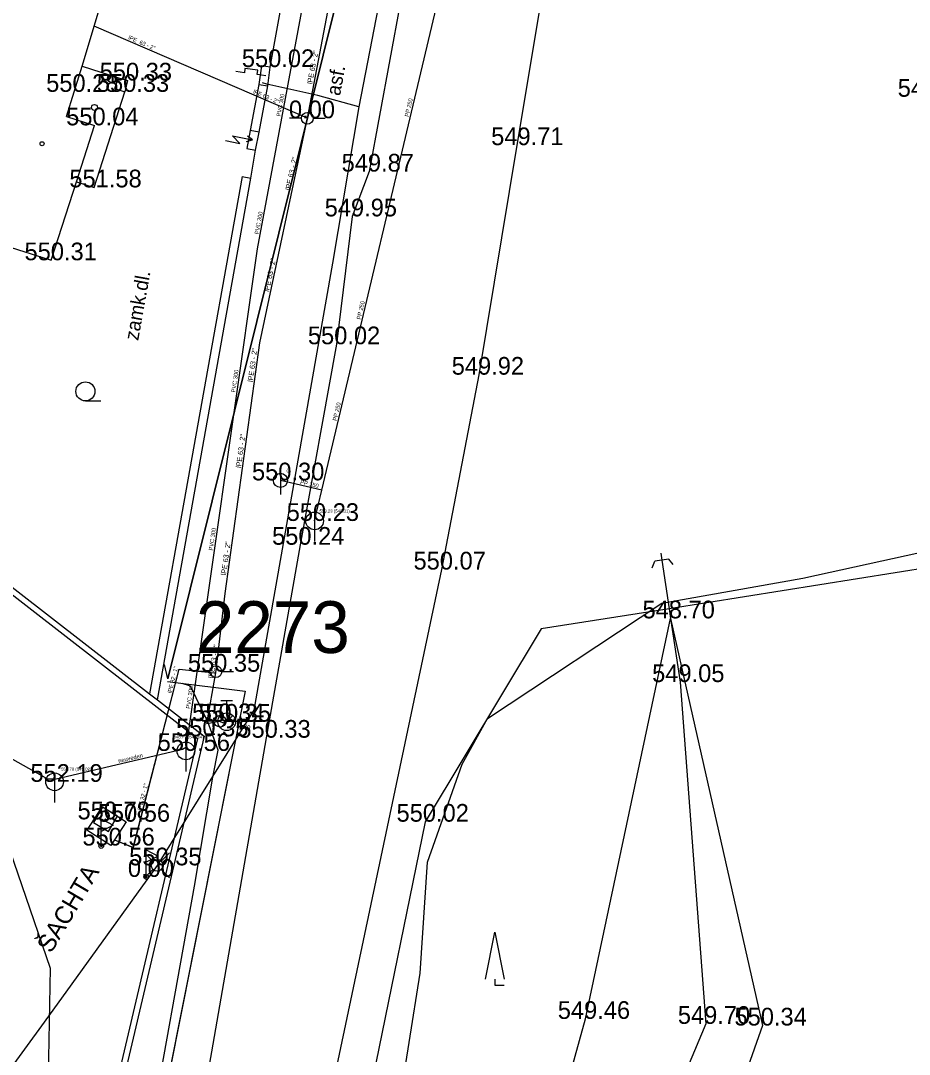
# Model space of a CAD drawing. Extents: x -669995 to -669686, y -1125551 to -1125263.
# Drawn here: x -669866.53 to -669828.84, y -1125464.59 to -1125420.77 of the extents above; entities that cross this region are included whole.
import ezdxf

# ---------------------------------------------------------------- set-up
doc = ezdxf.new("R2010")
doc.units = 0
for name, color, linetype in [('G_Bod_tecka', 7, 'Continuous'), ('G_Bod_vyska', 7, 'Continuous'), ('G_Breh_Teren', 7, 'Continuous'), ('G_Budovy-znacky', 7, 'Continuous'), ('G_Budovy_Objekty', 7, 'Continuous'), ('G_Budovy_vstupy', 7, 'Continuous'), ('G_Cesty_Schody', 7, 'Continuous'), ('G_Plochy_zpevnene', 7, 'Continuous'), ('G_Ploty', 7, 'Continuous'), ('G_Ploty_vstupy', 7, 'Continuous'), ('G_Popisy_povrchu', 7, 'Continuous'), ('G_Poznamky_odkaz', 7, 'Continuous'), ('G_Site-kanalizace', 7, 'Continuous'), ('G_Site-plynovod', 7, 'Continuous'), ('G_Site-Rozvadece', 7, 'Continuous'), ('G_Site-Sachty_N', 7, 'Continuous'), ('G_Site-vodovod', 7, 'Continuous'), ('G_Z_ELsilove_nadz_kotovane', 7, 'Continuous'), ('G_Z_ELsilove_podz_kotovane', 7, 'Continuous'), ('G_Z_KANAL_podz_kotovane', 7, 'Continuous'), ('G_Z_KANAL_podz_priblizne', 7, 'Continuous'), ('G_Z_PLYNY_podz_geodeticky', 7, 'Continuous'), ('G_Z_SPOJE_podz_geodeticky', 7, 'Continuous'), ('G_Z_VODA_podz_kotovane', 7, 'Continuous'), ('G_Zelen-okraj', 7, 'Continuous'), ('G_Zelen-Znacky', 7, 'Continuous'), ('Vrstva 1', 7, 'Continuous'), ('Vrstva 11', 7, 'Continuous'), ('Vrstva 13', 7, 'Continuous'), ('Vrstva 17', 7, 'Continuous'), ('Vrstva 2', 7, 'Continuous'), ('Vrstva 26', 7, 'Continuous'), ('Vrstva 3', 7, 'Continuous'), ('Vrstva 4', 7, 'Continuous'), ('Vrstva 5', 7, 'Continuous'), ('Vrstva 6', 7, 'Continuous'), ('Vrstva 7', 7, 'Continuous'), ('Vrstva 8', 7, 'Continuous')]:
    doc.layers.add(name, color=color, linetype=linetype)

msp = doc.modelspace()

# ---------------------------------------------------------------- linework, layer by layer
at = {"layer": 'G_Bod_tecka'}
for p, q in [((-669855.94, -1125422.74), (-669855.94, -1125422.74)), ((-669861.99, -1125423.31), (-669861.99, -1125423.31)), ((-669864.26, -1125423.79), (-669864.26, -1125423.79)), ((-669862.11, -1125423.79), (-669862.11, -1125423.79)), ((-669854.37, -1125424.91), (-669854.37, -1125424.91)), ((-669863.39, -1125425.21), (-669863.39, -1125425.21)), ((-669845.47, -1125426.05), (-669845.47, -1125426.05)), ((-669851.75, -1125427.17), (-669851.75, -1125427.17)), ((-669863.44, -1125427.84), (-669863.44, -1125427.84)), ((-669852.47, -1125429.07), (-669852.47, -1125429.07)), ((-669865.24, -1125430.93), (-669865.24, -1125430.93)), ((-669853.14, -1125434.49), (-669853.14, -1125434.49)), ((-669847.08, -1125435.78), (-669847.08, -1125435.78)), ((-669855.51, -1125440.26), (-669855.51, -1125440.26)), ((-669854.06, -1125441.98), (-669854.06, -1125441.98)), ((-669854.68, -1125442.99), (-669854.68, -1125442.99)), ((-669848.66, -1125444.04), (-669848.66, -1125444.04)), ((-669838.97, -1125446.11), (-669838.97, -1125446.11)), ((-669858.25, -1125448.37), (-669858.25, -1125448.37)), ((-669838.56, -1125448.81), (-669838.56, -1125448.81)), ((-669858.07, -1125450.47), (-669858.07, -1125450.47)), ((-669857.79, -1125450.49), (-669857.79, -1125450.49)), ((-669858.75, -1125451.11), (-669858.75, -1125451.11)), ((-669856.11, -1125451.17), (-669856.11, -1125451.17)), ((-669859.52, -1125451.73), (-669859.52, -1125451.73)), ((-669865.09, -1125453.04), (-669865.09, -1125453.04)), ((-669862.93, -1125454.63), (-669862.93, -1125454.63)), ((-669862.06, -1125454.73), (-669862.06, -1125454.73)), ((-669849.38, -1125454.73), (-669849.38, -1125454.73)), ((-669862.71, -1125455.74), (-669862.71, -1125455.74)), ((-669860.74, -1125456.58), (-669860.74, -1125456.58)), ((-669861.2, -1125457.07), (-669861.2, -1125457.07)), ((-669842.57, -1125463.09), (-669842.57, -1125463.09)), ((-669837.47, -1125463.3), (-669837.47, -1125463.3)), ((-669835.07, -1125463.37), (-669835.07, -1125463.37))]:
    msp.add_line(p, q, dxfattribs=at)
at = {"layer": 'G_Breh_Teren'}
for p, q in [((-669839.34, -1125443.64), (-669839.03, -1125445.7)), ((-669839.03, -1125445.7), (-669838.97, -1125446.11)), ((-669842.57, -1125463.09), (-669838.97, -1125446.11)), ((-669838.97, -1125446.11), (-669835.07, -1125463.37)), ((-669838.97, -1125446.11), (-669838.56, -1125448.81)), ((-669838.56, -1125448.81), (-669837.47, -1125463.3)), ((-669845.79, -1125474.65), (-669842.57, -1125463.09))]:
    msp.add_line(p, q, dxfattribs=at)
for points in [[(-669837.47, -1125463.3), (-669842.14, -1125474.41)], [(-669835.07, -1125463.37), (-669838.97, -1125474.44)]]:
    msp.add_lwpolyline(points, dxfattribs=at)
at = {"layer": 'G_Budovy-znacky'}
for centre, radius in [((-669863.4, -1125424.45), 0.125), ((-669865.619, -1125425.99), 0.0875)]:
    msp.add_circle(centre, radius, dxfattribs=at)
at = {"layer": 'G_Budovy_Objekty'}
for p, q in [((-669863.92, -1125422.7), (-669863.19, -1125420.26)), ((-669864.26, -1125423.79), (-669863.92, -1125422.7)), ((-669863.92, -1125422.7), (-669862.38, -1125423.19)), ((-669862.53, -1125423.65), (-669862.38, -1125423.19)), ((-669862.38, -1125423.19), (-669861.99, -1125423.31)), ((-669861.99, -1125423.31), (-669862.11, -1125423.79)), ((-669863.41, -1125427.84), (-669862.11, -1125423.79)), ((-669862.53, -1125423.65), (-669862.11, -1125423.79)), ((-669864.58, -1125424.83), (-669863.39, -1125425.21)), ((-669864.16, -1125427.6), (-669863.39, -1125425.21)), ((-669877.15, -1125427.12), (-669865.24, -1125430.93)), ((-669865.24, -1125430.93), (-669864.16, -1125427.6)), ((-669864.16, -1125427.6), (-669863.41, -1125427.84))]:
    msp.add_line(p, q, dxfattribs=at)
at = {"layer": 'G_Budovy_vstupy'}
msp.add_line((-669864.58, -1125424.83), (-669864.26, -1125423.79), dxfattribs=at)
at = {"layer": 'G_Cesty_Schody'}
for p, q in [((-669863.07, -1125454.08), (-669863.72, -1125455.09)), ((-669863.07, -1125454.08), (-669862.06, -1125454.73)), ((-669862.06, -1125454.73), (-669862.71, -1125455.74)), ((-669862.71, -1125455.74), (-669863.72, -1125455.09))]:
    msp.add_line(p, q, dxfattribs=at)
at = {"layer": 'G_Plochy_zpevnene'}
for p, q in [((-669845.47, -1125426.05), (-669843.77, -1125415.85)), ((-669850.43, -1125420.04), (-669851.75, -1125427.17)), ((-669847.08, -1125435.78), (-669845.47, -1125426.05)), ((-669851.75, -1125427.17), (-669852.47, -1125429.07)), ((-669852.47, -1125429.07), (-669853.14, -1125434.49)), ((-669853.14, -1125434.49), (-669854.68, -1125442.99)), ((-669848.66, -1125444.04), (-669847.08, -1125435.78)), ((-669857.76, -1125487.1), (-669848.66, -1125444.04))]:
    msp.add_line(p, q, dxfattribs=at)
msp.add_lwpolyline([(-669854.68, -1125442.99), (-669856.11, -1125451.17), (-669858.7, -1125466.02)], dxfattribs=at)
at = {"layer": 'G_Ploty'}
for p, q in [((-669856.43, -1125423.48), (-669856.79, -1125425.43)), ((-669856.42, -1125425.5), (-669856.05, -1125423.53)), ((-669857.14, -1125427.38), (-669861.07, -1125449.31)), ((-669860.73, -1125449.57), (-669856.77, -1125427.45)), ((-669857.14, -1125427.38), (-669856.77, -1125427.45)), ((-669878.91, -1125435.78), (-669859.03, -1125451.21)), ((-669859.03, -1125451.21), (-669864.64, -1125475.11)), ((-669858.75, -1125451.11), (-669864.36, -1125475.01))]:
    msp.add_line(p, q, dxfattribs=at)
msp.add_lwpolyline([(-669879.12, -1125435.3), (-669861.07, -1125449.31), (-669860.73, -1125449.57), (-669858.75, -1125451.11)], dxfattribs=at)
at = {"layer": 'G_Ploty_vstupy'}
for p, q in [((-669855.94, -1125422.74), (-669855.39, -1125419.71)), ((-669856.77, -1125427.45), (-669856.57, -1125426.26))]:
    msp.add_line(p, q, dxfattribs=at)
at = {"layer": 'G_Site-kanalizace'}
for p, q in [((-669855.51, -1125439.96), (-669855.51, -1125440.86)), ((-669854.06, -1125441.605), (-669854.06, -1125442.855)), ((-669839.385, -1125443.343), (-669839.34, -1125443.64)), ((-669839.746, -1125443.965), (-669839.637, -1125443.685)), ((-669839.34, -1125443.64), (-669839.637, -1125443.685)), ((-669839.043, -1125443.595), (-669839.34, -1125443.64)), ((-669838.856, -1125443.83), (-669839.043, -1125443.595)), ((-669859.52, -1125451.355), (-669859.52, -1125452.605)), ((-669865.09, -1125452.665), (-669865.09, -1125453.915))]:
    msp.add_line(p, q, dxfattribs=at)
for centre, radius in [((-669855.51, -1125440.26), 0.3), ((-669854.06, -1125441.98), 0.375), ((-669859.52, -1125451.73), 0.375), ((-669865.09, -1125453.04), 0.375)]:
    msp.add_circle(centre, radius, dxfattribs=at)
at = {"layer": 'G_Site-plynovod'}
for p, q in [((-669863.11, -1125455.76), (-669863.11, -1125454.61)), ((-669863.11, -1125454.61), (-669862.61, -1125454.875)), ((-669862.61, -1125454.875), (-669863.11, -1125455.14)), ((-669861.272, -1125456.048), (-669860.917, -1125456.403)), ((-669861.2, -1125457.07), (-669861.2, -1125455.92)), ((-669861.2, -1125455.92), (-669860.7, -1125456.185)), ((-669860.7, -1125456.185), (-669861.2, -1125456.45)), ((-669860.563, -1125456.402), (-669860.209, -1125456.049)), ((-669860.917, -1125456.756), (-669861.27, -1125457.11)), ((-669860.564, -1125456.755), (-669860.209, -1125457.11))]:
    msp.add_line(p, q, dxfattribs=at)
for centre, radius in [((-669863.11, -1125455.76), 0.1), ((-669863.11, -1125455.76), 0.0348), ((-669860.74, -1125456.58), 0.25), ((-669861.2, -1125457.07), 0.1), ((-669861.2, -1125457.07), 0.0348)]:
    msp.add_circle(centre, radius, dxfattribs=at)
at = {"layer": 'G_Site-Rozvadece'}
for p, q in [((-669857.843, -1125425.858), (-669857.228, -1125425.979)), ((-669857.228, -1125425.979), (-669857.548, -1125425.661)), ((-669857.548, -1125425.661), (-669856.69, -1125425.83)), ((-669856.951, -1125425.891), (-669856.69, -1125425.83)), ((-669856.69, -1125425.83), (-669856.909, -1125425.675))]:
    msp.add_line(p, q, dxfattribs=at)
msp.add_lwpolyline([(-669856.13, -1125423.11), (-669856.494, -1125423.059), (-669856.469, -1125422.877), (-669857.015, -1125422.801), (-669857.042, -1125422.982), (-669857.406, -1125422.933)], dxfattribs=at)
for points in [[(-669855.94, -1125422.74), (-669856.32, -1125422.69), (-669856.43, -1125423.48), (-669856.05, -1125423.53)], [(-669856.42, -1125425.5), (-669856.79, -1125425.43), (-669856.94, -1125426.19), (-669856.57, -1125426.26)]]:
    msp.add_lwpolyline(points, close=True, dxfattribs=at)
at = {"layer": 'G_Site-Sachty_N'}
msp.add_lwpolyline([(-669863.444, -1125454.762), (-669862.798, -1125455.144), (-669862.416, -1125454.498), (-669863.062, -1125454.116)], close=True, dxfattribs=at)
msp.add_circle((-669862.93, -1125454.63), 0.02, dxfattribs=at)
at = {"layer": 'G_Site-vodovod'}
for p, q in [((-669854.62, -1125424.91), (-669855.12, -1125424.91)), ((-669854.12, -1125424.91), (-669853.62, -1125424.91)), ((-669858.5, -1125448.37), (-669859, -1125448.37)), ((-669858, -1125448.37), (-669857.5, -1125448.37)), ((-669858.04, -1125449.59), (-669857.54, -1125449.59)), ((-669857.79, -1125450.115), (-669857.79, -1125449.59)), ((-669858.32, -1125450.47), (-669858.82, -1125450.47)), ((-669858.055, -1125450.755), (-669857.525, -1125450.225)), ((-669857.82, -1125450.47), (-669857.32, -1125450.47))]:
    msp.add_line(p, q, dxfattribs=at)
for centre, radius in [((-669854.37, -1125424.91), 0.25), ((-669858.25, -1125448.37), 0.25), ((-669857.79, -1125450.49), 0.375), ((-669858.07, -1125450.47), 0.25)]:
    msp.add_circle(centre, radius, dxfattribs=at)
at = {"layer": 'G_Z_ELsilove_nadz_kotovane'}
for points in [[(-669860.28, -1125448.68), (-669849.93, -1125407.07)], [(-669860.28, -1125448.68), (-669860.43, -1125448.062)]]:
    msp.add_lwpolyline(points, dxfattribs=at)
at = {"layer": 'G_Z_ELsilove_podz_kotovane'}
for points in [[(-669793.678, -1125277.309), (-669806.73, -1125294.49), (-669822.69, -1125326.67), (-669837.43, -1125364.93), (-669849.93, -1125407.07), (-669860.28, -1125448.68)], [(-669863.576, -1125550.524), (-669862.33, -1125537.01), (-669860.37, -1125518.38), (-669858.01, -1125505.29), (-669856.03, -1125494.7), (-669852.89, -1125480.26), (-669850.98, -1125469.97), (-669849.59, -1125461.15), (-669849.27, -1125456.45), (-669847.81, -1125452.29), (-669846.73, -1125450.36), (-669839.33, -1125445.47), (-669833.36, -1125444.41), (-669826.21, -1125442.84), (-669824.2, -1125441.7), (-669823.97, -1125438.88), (-669824.78, -1125429.63), (-669825.67, -1125424.25), (-669825.82, -1125421.69), (-669825.4, -1125420.37)], [(-669860.3, -1125448.78), (-669857.01, -1125449.2), (-669865.7, -1125492.91), (-669865.7, -1125492.92), (-669866.34, -1125496.64), (-669873.15, -1125519.21), (-669881.89, -1125548.16)], [(-669883.381, -1125547.971), (-669882.5, -1125544.29), (-669880.2, -1125536.8), (-669877.05, -1125527.79), (-669873.99, -1125518.65), (-669873.17, -1125517.76), (-669871.78, -1125517.42), (-669870.84, -1125517.03), (-669870.63, -1125516.39), (-669866.12, -1125495.04), (-669865.96, -1125494.25), (-669863.58, -1125480.59), (-669861.15, -1125468.54), (-669859.15, -1125457.46), (-669858.38, -1125452.84), (-669858.15, -1125451.7), (-669858.59, -1125450.49), (-669859.33, -1125448.99), (-669859.674, -1125448.873)]]:
    msp.add_lwpolyline(points, dxfattribs=at)
at = {"layer": 'G_Z_KANAL_podz_kotovane'}
msp.add_line((-669853.75, -1125440.68), (-669855.51, -1125440.26), dxfattribs=at)
for points in [[(-669854.06, -1125441.98), (-669853.75, -1125440.68), (-669848.77, -1125419.63), (-669845.09, -1125404.08), (-669844.67, -1125402.32)], [(-669884.87, -1125442.37), (-669884.3, -1125442.3), (-669865.39, -1125452.91), (-669865.02, -1125452.92), (-669859.66, -1125451.66), (-669859.5, -1125451.55)]]:
    msp.add_lwpolyline(points, dxfattribs=at)
at = {"layer": 'G_Z_KANAL_podz_priblizne'}
msp.add_lwpolyline([(-669859.5, -1125451.55), (-669856.48, -1125430.45), (-669853.73, -1125415.63), (-669852.14, -1125407.38), (-669851.85, -1125406.81), (-669846.78, -1125392.66), (-669840.64, -1125375.45), (-669843.45, -1125370.23)], dxfattribs=at)
at = {"layer": 'G_Z_PLYNY_podz_geodeticky'}
for points in [[(-669839.68, -1125381.34), (-669843.56, -1125391.5), (-669845.77, -1125398.22), (-669846.85, -1125401.64), (-669847.2, -1125402.75), (-669848.28, -1125405.76), (-669848.45, -1125406.31), (-669848.51, -1125406.54), (-669849.81, -1125412.17), (-669852.19, -1125424.43), (-669853.31, -1125431.05), (-669856.64, -1125450), (-669860.14, -1125455.63), (-669860.74, -1125456.58)], [(-669852.19, -1125424.43), (-669853.93, -1125423.95), (-669856.09, -1125423.46), (-669856.27, -1125423.41)], [(-669860.74, -1125456.58), (-669864.36, -1125461.6), (-669865.53, -1125463.23), (-669867.2, -1125465.52), (-669868.44, -1125468.41), (-669874.13, -1125486.27), (-669879.55, -1125501.34), (-669881.43, -1125507.04), (-669885.9, -1125530.75), (-669889.237, -1125547.216)]]:
    msp.add_lwpolyline(points, dxfattribs=at)
at = {"layer": 'G_Z_SPOJE_podz_geodeticky'}
msp.add_lwpolyline([(-669868.9, -1125450.43), (-669865.28, -1125460.94), (-669865.56, -1125476.2), (-669868.62, -1125490.28), (-669873.32, -1125500), (-669873.84, -1125501.08), (-669875.38, -1125507.75), (-669876.44, -1125519.45), (-669880.16, -1125533.89), (-669884.345, -1125547.846)], dxfattribs=at)
at = {"layer": 'G_Z_VODA_podz_kotovane'}
msp.add_line((-669854.37, -1125424.91), (-669863.41, -1125421), dxfattribs=at)
for points in [[(-669858.63, -1125450.57), (-669858.25, -1125448.42), (-669857.85, -1125445.05), (-669856.38, -1125434.43), (-669854.37, -1125424.91), (-669851.09, -1125407.69), (-669849.25, -1125402.21), (-669840.03, -1125375.63), (-669840.08, -1125374.27), (-669839.76, -1125372.61), (-669839.5, -1125370.59), (-669837.98, -1125365.03), (-669838.35, -1125363.15), (-669838.04, -1125362.68), (-669836.94, -1125362.97)], [(-669862.55, -1125455.5), (-669861.75, -1125455.82), (-669859.81, -1125448.27), (-669858.31, -1125448.42), (-669858.25, -1125448.42)], [(-669858.63, -1125450.57), (-669858.11, -1125450.47), (-669857.85, -1125450.57)]]:
    msp.add_lwpolyline(points, dxfattribs=at)
at = {"layer": 'G_Zelen-okraj'}
for p, q in [((-669824.81, -1125443.45), (-669839.03, -1125445.7)), ((-669839.03, -1125445.7), (-669844.46, -1125446.56)), ((-669844.46, -1125446.56), (-669849.38, -1125454.73)), ((-669849.38, -1125454.73), (-669853.07, -1125472.79))]:
    msp.add_line(p, q, dxfattribs=at)
at = {"layer": 'G_Zelen-Znacky'}
for p, q in [((-669863.782, -1125436.89), (-669863.132, -1125436.887)), ((-669846.82, -1125461.41), (-669846.42, -1125459.41)), ((-669846.42, -1125459.41), (-669846.02, -1125461.41)), ((-669846.42, -1125461.41), (-669846.42, -1125461.66)), ((-669846.42, -1125461.66), (-669846.02, -1125461.66))]:
    msp.add_line(p, q, dxfattribs=at)
msp.add_circle((-669863.782, -1125436.487), 0.403, dxfattribs=at)
at = {"layer": 'Vrstva 1'}
msp.add_line((-669860.3, -1125448.78), (-669860.3, -1125448.78), dxfattribs=at)
at = {"layer": 'Vrstva 11'}
msp.add_line((-669853.75, -1125440.68), (-669855.51, -1125440.26), dxfattribs=at)
msp.add_lwpolyline([(-669854.06, -1125441.98), (-669853.75, -1125440.68), (-669848.77, -1125419.63), (-669845.09, -1125404.08), (-669844.67, -1125402.32)], dxfattribs=at)
at = {"layer": 'Vrstva 13'}
msp.add_lwpolyline([(-669885.03, -1125442.78), (-669884.87, -1125442.37), (-669884.3, -1125442.3), (-669865.39, -1125452.91), (-669865.02, -1125452.92), (-669859.66, -1125451.66), (-669859.5, -1125451.55)], dxfattribs=at)
at = {"layer": 'Vrstva 17'}
for p, q in [((-669860.3, -1125448.78), (-669857.01, -1125449.2)), ((-669857.01, -1125449.2), (-669865.7, -1125492.91))]:
    msp.add_line(p, q, dxfattribs=at)
msp.add_lwpolyline([(-669859.5, -1125451.55), (-669856.48, -1125430.45), (-669853.73, -1125415.63), (-669852.14, -1125407.38), (-669851.85, -1125406.81), (-669846.78, -1125392.66), (-669840.64, -1125375.45), (-669843.45, -1125370.23)], dxfattribs=at)
at = {"layer": 'Vrstva 26'}
msp.add_line((-669854.37, -1125424.91), (-669863.411, -1125421), dxfattribs=at)
for points in [[(-669858.63, -1125450.57), (-669858.245, -1125448.421), (-669857.85, -1125445.05), (-669856.38, -1125434.43), (-669854.37, -1125424.91), (-669851.09, -1125407.69), (-669849.25, -1125402.21), (-669840.03, -1125375.63), (-669840.08, -1125374.27), (-669839.76, -1125372.61), (-669839.5, -1125370.59), (-669837.98, -1125365.03), (-669838.35, -1125363.15), (-669838.04, -1125362.68), (-669836.94, -1125362.97)], [(-669862.551, -1125455.498), (-669861.745, -1125455.825), (-669859.807, -1125448.265), (-669858.306, -1125448.415), (-669858.245, -1125448.421)], [(-669858.63, -1125450.57), (-669858.11, -1125450.47), (-669857.85, -1125450.57)]]:
    msp.add_lwpolyline(points, dxfattribs=at)
at = {"layer": 'Vrstva 5'}
msp.add_line((-669849.93, -1125407.07), (-669860.28, -1125448.68), dxfattribs=at)
at = {"layer": 'Vrstva 6'}
for p, q in [((-669854.37, -1125424.91), (-669854.37, -1125424.91)), ((-669858.306, -1125448.415), (-669858.306, -1125448.415)), ((-669858.11, -1125450.47), (-669858.11, -1125450.47))]:
    msp.add_line(p, q, dxfattribs=at)
at = {"layer": 'Vrstva 7'}
msp.add_line((-669857.85, -1125450.57), (-669857.85, -1125450.57), dxfattribs=at)
at = {"layer": 'Vrstva 8'}
for p, q in [((-669855.51, -1125440.26), (-669855.51, -1125440.26)), ((-669854.06, -1125441.98), (-669854.06, -1125441.98)), ((-669859.5, -1125451.55), (-669859.5, -1125451.55)), ((-669865.02, -1125452.92), (-669865.02, -1125452.92))]:
    msp.add_line(p, q, dxfattribs=at)

# ---------------------------------------------------------------- texts
at = {"layer": 'G_Bod_vyska'}
for s, p in [('550.02', (-669857.147, -1125422.74)), ('550.33', (-669863.176, -1125423.31)), ('550.28', (-669865.446, -1125423.79)), ('550.33', (-669863.296, -1125423.79)), ('549.13', (-669829.334, -1125424)), ('0.00', (-669855.15, -1125424.91)), ('550.04', (-669864.597, -1125425.21)), ('549.71', (-669846.574, -1125426.05)), ('549.87', (-669852.916, -1125427.17)), ('551.58', (-669864.462, -1125427.84)), ('549.95', (-669853.635, -1125429.07)), ('550.31', (-669866.364, -1125430.93)), ('550.02', (-669854.347, -1125434.49)), ('549.92', (-669848.248, -1125435.78)), ('550.30', (-669856.717, -1125440.26)), ('550.23', (-669855.246, -1125441.98)), ('550.24', (-669855.866, -1125442.99)), ('550.07', (-669849.867, -1125444.04)), ('548.70', (-669840.156, -1125446.11)), ('550.35', (-669859.436, -1125448.37)), ('549.05', (-669839.748, -1125448.81)), ('550.34', (-669859.256, -1125450.47)), ('550.35', (-669858.976, -1125450.49)), ('550.35', (-669859.936, -1125451.11)), ('550.33', (-669857.296, -1125451.17)), ('550.56', (-669860.719, -1125451.73)), ('552.19', (-669866.114, -1125453.04)), ('550.78', (-669864.116, -1125454.63)), ('550.56', (-669863.259, -1125454.73)), ('550.02', (-669850.587, -1125454.73)), ('550.56', (-669863.909, -1125455.74)), ('550.35', (-669861.926, -1125456.58)), ('0.00', (-669861.98, -1125457.07)), ('549.46', (-669843.75, -1125463.09)), ('549.70', (-669838.658, -1125463.3)), ('550.34', (-669836.256, -1125463.37))]:
    msp.add_text(s, height=0.75, dxfattribs=at).set_placement(p)
at = {"layer": 'G_Popisy_povrchu'}
for s, rotation, p in [('asf.', 79.5114, (-669852.988, -1125423.985)), ('zamk.dl.', 79.8545, (-669861.544, -1125434.362))]:
    msp.add_text(s, height=0.6, rotation=rotation, dxfattribs=at).set_placement(p)
at = {"layer": 'G_Poznamky_odkaz'}
msp.add_text('ŠACHTA', height=0.75, rotation=59.4028, dxfattribs=at).set_placement((-669865.237, -1125460.345))
at = {"layer": 'Vrstva 2'}
for s, height, p in [('\xa0()', 0.1316, (-669855.305, -1125439.907)), ('550.23 (548.01)', 0.13163, (-669853.854, -1125441.627)), ('548.77 (548.64)', 0.13163, (-669860.046, -1125451.197)), ('550.78 (549.02)', 0.13163, (-669864.814, -1125452.567))]:
    msp.add_text(s, height=height, dxfattribs=at).set_placement(p)
at = {"layer": 'Vrstva 3'}
for s, rotation, p in [('PVC 300', 79.537, (-669855.511, -1125424.843)), ('PP 250', 76.7029, (-669850.078, -1125424.862)), ('PVC 300', 79.537, (-669856.437, -1125429.838)), ('PP 250', 76.6934, (-669852.115, -1125433.455)), ('PVC 300', 81.8747, (-669857.423, -1125436.54)), ('PP 250', 76.7029, (-669853.132, -1125437.752)), ('PP 150', 346.5827, (-669854.685, -1125440.403)), ('PVC 300', 81.841, (-669858.382, -1125443.245)), ('PVC 300', 81.8795, (-669859.343, -1125449.951)), ('neuveden', 13.2975, (-669862.368, -1125452.243))]:
    msp.add_text(s, height=0.1755, rotation=rotation, dxfattribs=at).set_placement(p)
at = {"layer": 'Vrstva 4'}
for s, height, rotation, p in [('lPE  63 - 2"', 0.17551, 336.6922, (-669861.982, -1125421.552)), ('lPE 63 - 2"', 0.21938, 79.2429, (-669854.169, -1125423.478)), ('lPE 63 - 2"', 0.17551, 336.6601, (-669856.686, -1125423.841)), ('lPE 63 - 2"', 0.21938, 78.0825, (-669855.091, -1125427.98)), ('lPE 63 - 2"', 0.21938, 78.0888, (-669855.997, -1125432.279)), ('lPE 63 - 2"', 0.21938, 82.1496, (-669856.683, -1125436.102)), ('lPE 63 - 2"', 0.21938, 82.1496, (-669857.187, -1125439.745)), ('lPE 63 - 2"', 0.21938, 82.1709, (-669857.818, -1125444.298)), ('lPE 63 - 2"', 0.21938, 80.2476, (-669858.363, -1125448.664)), ('lPE 32 - 1"', 0.17551, 75.6767, (-669860.136, -1125449.294)), ('LT 80', 0.2194, 338.9445, (-669857.558, -1125450.607)), ('lPE 32 - 1"', 0.17551, 75.7028, (-669861.408, -1125454.256))]:
    msp.add_text(s, height=height, rotation=rotation, dxfattribs=at).set_placement(p)
msp.add_text('2273', height=2.1939, dxfattribs=at).set_placement((-669859.097, -1125447.578))

doc.saveas('drawing.dxf')
